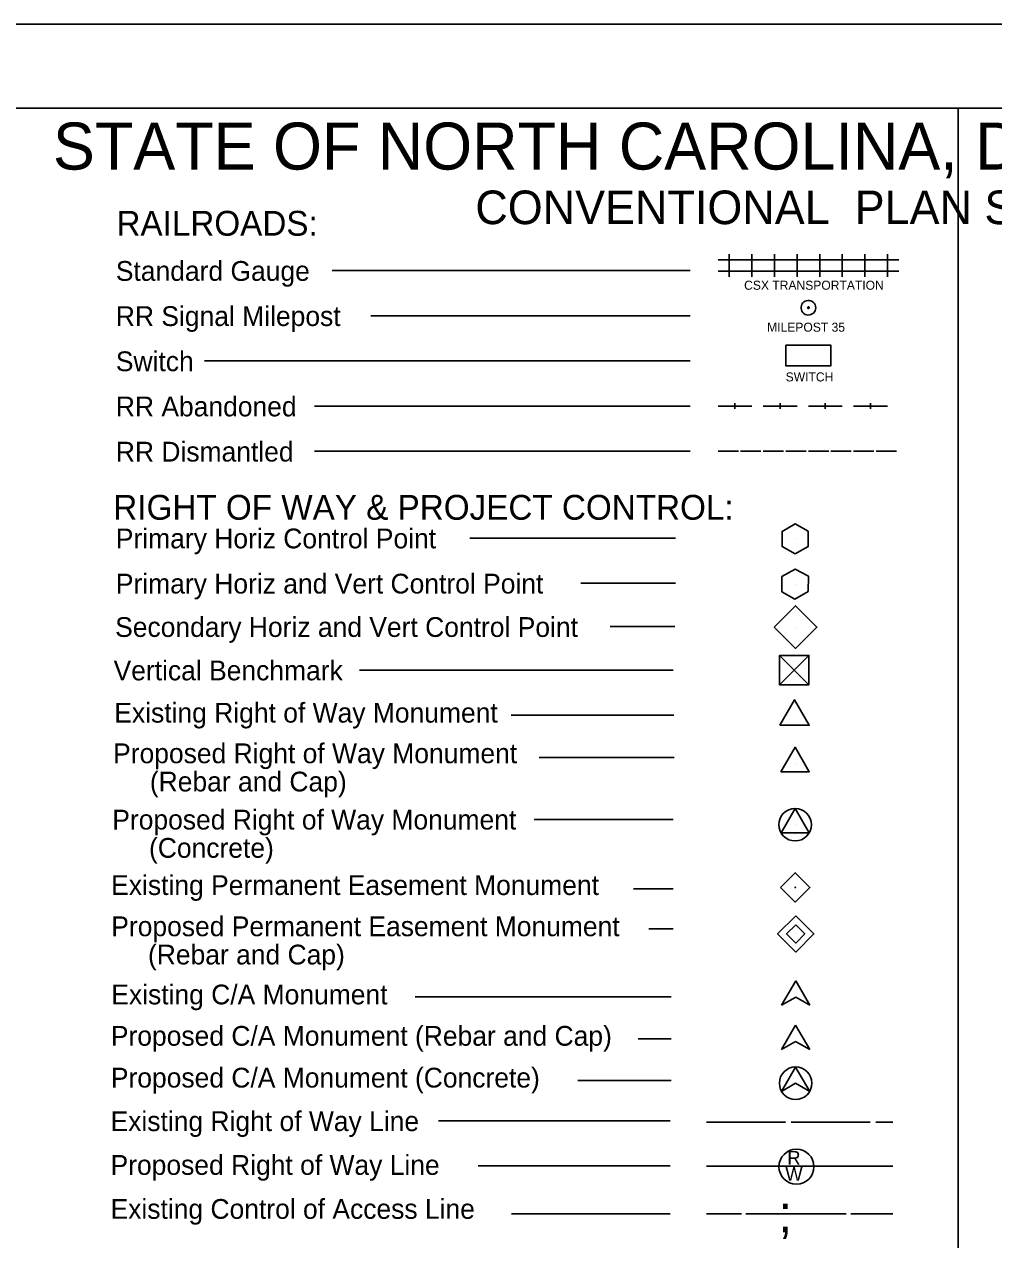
# Model space of a CAD drawing. Extents: x -0.53 to 3.34, y -0.27 to 4.33.
# Drawn here: x 0.939 to 1.661, y 3.424 to 4.328 of the extents above; entities that cross this region are included whole.
import ezdxf

# ---------------------------------------------------------------- set-up
doc = ezdxf.new("R2010")
doc.units = 0
for name, color, linetype in [('P_RDY_ROW_Permanent_Easement', 7, 'Continuous'), ('Sheet_Plan', 7, 'Continuous'), ('Sheet_Symbology', 7, 'Continuous'), ('z - Construction', 7, 'Continuous')]:
    doc.layers.add(name, color=color, linetype=linetype)

msp = doc.modelspace()

# ---------------------------------------------------------------- linework, layer by layer
at = {"layer": 'P_RDY_ROW_Permanent_Easement'}
msp.add_line((1.5132, 3.65135), (1.5132, 3.65135), dxfattribs=at)
for points in [[(1.5132, 3.66489), (1.52674, 3.65135), (1.5132, 3.63781), (1.49966, 3.65135)], [(1.5132, 3.65812), (1.51997, 3.65135), (1.5132, 3.64458), (1.50643, 3.65135)]]:
    msp.add_lwpolyline(points, close=True, dxfattribs=at)
at = {"layer": 'Sheet_Plan'}
msp.add_line((2.98823, 4.26594), (0.2799, 4.26594), dxfattribs=at)
at = {"layer": 'Sheet_Symbology'}
for p, q in [((1.45536, 4.15312), (1.47217, 4.15312)), ((1.46377, 4.14051), (1.46377, 4.15732)), ((1.47217, 4.15312), (1.48899, 4.15312)), ((1.48058, 4.14051), (1.48058, 4.15732)), ((1.48899, 4.15312), (1.50581, 4.15312)), ((1.4974, 4.14051), (1.4974, 4.15732)), ((1.50581, 4.15312), (1.52262, 4.15312)), ((1.51421, 4.14051), (1.51421, 4.15732)), ((1.52262, 4.15312), (1.53944, 4.15312)), ((1.53103, 4.14051), (1.53103, 4.15732)), ((1.53944, 4.15312), (1.55625, 4.15312)), ((1.54785, 4.14051), (1.54785, 4.15732)), ((1.55625, 4.15312), (1.57307, 4.15312)), ((1.56466, 4.14051), (1.56466, 4.15732)), ((1.57307, 4.15312), (1.58988, 4.15312)), ((1.58148, 4.14051), (1.58148, 4.15732)), ((1.43452, 4.14511), (1.16814, 4.14511)), ((1.45536, 4.14471), (1.47217, 4.14471)), ((1.47217, 4.14471), (1.48899, 4.14471)), ((1.48899, 4.14471), (1.50581, 4.14471)), ((1.50581, 4.14471), (1.52262, 4.14471)), ((1.52262, 4.14471), (1.53944, 4.14471)), ((1.53944, 4.14471), (1.55625, 4.14471)), ((1.55625, 4.14471), (1.57307, 4.14471)), ((1.57307, 4.14471), (1.58988, 4.14471)), ((1.43452, 4.11148), (1.19696, 4.11148)), ((1.43452, 4.07785), (1.07313, 4.07785)), ((1.43452, 4.04422), (1.15511, 4.04422)), ((1.45536, 4.04422), (1.48058, 4.04422)), ((1.46797, 4.04632), (1.46797, 4.04212)), ((1.48899, 4.04422), (1.51421, 4.04422)), ((1.5016, 4.04632), (1.5016, 4.04212)), ((1.52262, 4.04422), (1.54785, 4.04422)), ((1.53523, 4.04632), (1.53523, 4.04212)), ((1.55625, 4.04422), (1.58148, 4.04422)), ((1.56886, 4.04632), (1.56886, 4.04212)), ((1.43452, 4.01059), (1.15511, 4.01059)), ((1.43452, 4.01059), (1.15511, 4.01059)), ((1.45536, 4.01059), (1.47049, 4.01059)), ((1.47217, 4.01059), (1.48731, 4.01059)), ((1.48899, 4.01059), (1.50412, 4.01059)), ((1.50581, 4.01059), (1.52094, 4.01059)), ((1.52262, 4.01059), (1.53776, 4.01059)), ((1.53944, 4.01059), (1.55457, 4.01059)), ((1.55625, 4.01059), (1.57139, 4.01059)), ((1.57307, 4.01059), (1.5882, 4.01059)), ((1.42374, 3.94603), (1.27067, 3.94603)), ((1.51275, 3.9454), (1.51275, 3.9454)), ((1.42374, 3.9124), (1.35325, 3.9124)), ((1.51273, 3.91183), (1.51273, 3.91183)), ((1.42322, 3.8801), (1.3752, 3.8801)), ((1.51297, 3.87975), (1.51297, 3.87975)), ((1.42206, 3.84778), (1.18859, 3.84778)), ((1.51212, 3.8478), (1.51212, 3.8478)), ((1.42258, 3.81418), (1.30142, 3.81418)), ((1.42275, 3.78259), (1.32231, 3.78259)), ((1.51274, 3.7782), (1.51274, 3.7782)), ((1.42191, 3.73651), (1.31851, 3.73651)), ((1.51277, 3.73269), (1.51277, 3.73269)), ((1.42204, 3.6849), (1.39253, 3.6849)), ((1.5129, 3.686), (1.5129, 3.686)), ((1.42204, 3.65527), (1.40387, 3.65527)), ((1.50266, 3.59825), (1.51317, 3.61641)), ((1.51317, 3.61641), (1.52368, 3.59825)), ((1.42037, 3.60446), (1.22995, 3.60446)), ((1.51317, 3.60431), (1.50266, 3.59825)), ((1.52368, 3.59825), (1.51317, 3.60431)), ((1.50261, 3.56527), (1.51312, 3.58343)), ((1.51312, 3.58343), (1.52363, 3.56527)), ((1.42054, 3.57329), (1.39604, 3.57329)), ((1.51312, 3.57133), (1.50261, 3.56527)), ((1.52363, 3.56527), (1.51312, 3.57133)), ((1.50261, 3.53415), (1.51312, 3.55231)), ((1.51312, 3.55231), (1.52363, 3.53415)), ((1.42054, 3.54217), (1.35093, 3.54217)), ((1.51312, 3.54021), (1.50261, 3.53415)), ((1.52363, 3.53415), (1.51312, 3.54021)), ((1.4198, 3.51227), (1.24741, 3.51227)), ((1.44675, 3.51131), (1.50561, 3.51131)), ((1.50981, 3.51131), (1.56867, 3.51131)), ((1.57287, 3.51131), (1.58548, 3.51131)), ((1.4198, 3.47864), (1.27679, 3.47864)), ((1.44675, 3.47843), (1.58548, 3.47843)), ((1.4198, 3.44312), (1.30168, 3.44312)), ((1.44675, 3.44312), (1.47275, 3.44312)), ((1.47612, 3.44312), (1.5508, 3.44312)), ((1.55416, 3.44312), (1.58548, 3.44312))]:
    msp.add_line(p, q, dxfattribs=at)
for points in [[(1.52811, 4.11747), (1.52799, 4.11856), (1.52767, 4.11965), (1.52712, 4.12063), (1.52636, 4.1214), (1.52548, 4.12205), (1.5245, 4.1226), (1.52352, 4.12282), (1.52231, 4.12293), (1.52122, 4.12271), (1.52024, 4.12238), (1.51926, 4.12183), (1.51849, 4.12107), (1.51784, 4.12009), (1.5174, 4.1191), (1.51718, 4.11801), (1.51718, 4.11692), (1.5174, 4.11583), (1.51784, 4.11485), (1.51849, 4.11386), (1.51926, 4.1131), (1.52024, 4.11255), (1.52122, 4.11222), (1.52231, 4.112), (1.52352, 4.11211), (1.5245, 4.11233), (1.52548, 4.11288), (1.52636, 4.11353), (1.52712, 4.1143), (1.52767, 4.11528), (1.52799, 4.11637), (1.52811, 4.11747)], [(1.52286, 4.11812), (1.52253, 4.11812), (1.52221, 4.1179), (1.52199, 4.11758), (1.5221, 4.11725), (1.52231, 4.11692), (1.52264, 4.11681), (1.52297, 4.11692), (1.52319, 4.11714), (1.5233, 4.11758), (1.52319, 4.1179), (1.52286, 4.11812)], [(1.51275, 3.93422), (1.503, 3.93975), (1.503, 3.95094), (1.51275, 3.95659), (1.5225, 3.95106), (1.5225, 3.93975), (1.51275, 3.93422)], [(1.52301, 3.85869), (1.5012, 3.83688), (1.5121, 3.84778), (1.52301, 3.83688), (1.5012, 3.85869)], [(1.5121, 3.84778), (1.52301, 3.85869), (1.5012, 3.85869), (1.5121, 3.84778)], [(1.5121, 3.84778), (1.5012, 3.83688), (1.52301, 3.83688), (1.5121, 3.84778)], [(1.50137, 3.80668), (1.51229, 3.82565), (1.52322, 3.80668), (1.50137, 3.80668)]]:
    msp.add_lwpolyline(points, dxfattribs=at)
for points in [[(1.50581, 4.08956), (1.53944, 4.08956), (1.53944, 4.07426), (1.50581, 4.07426)], [(1.50293, 3.9175), (1.51279, 3.923), (1.52265, 3.91758), (1.5225, 3.90628), (1.51264, 3.90055), (1.50293, 3.90605)], [(1.49714, 3.87981), (1.51305, 3.89571), (1.52898, 3.87978), (1.51307, 3.86387)], [(1.5012, 3.85869), (1.52301, 3.85869), (1.52301, 3.83688), (1.5012, 3.83688)], [(1.50223, 3.77214), (1.51274, 3.7903), (1.52325, 3.77214)], [(1.50226, 3.72664), (1.51277, 3.7448), (1.52328, 3.72664)], [(1.50198, 3.686), (1.5129, 3.69693), (1.52382, 3.686), (1.5129, 3.67508)]]:
    msp.add_lwpolyline(points, close=True, dxfattribs=at)
for centre, radius in [((1.51277, 3.73269), 0.01211), ((1.5129, 3.686), 0.000212), ((1.51312, 3.54021), 0.01211), ((1.51377, 3.47809), 0.01304)]:
    msp.add_circle(centre, radius, dxfattribs=at)
at = {"layer": 'z - Construction'}
for p, q in [((3.05073, 4.32844), (0.2174, 4.32844)), ((1.63406, 4.26594), (1.63402, 2.55761))]:
    msp.add_line(p, q, dxfattribs=at)

# ---------------------------------------------------------------- texts
at = {"layer": 'Sheet_Symbology'}
for s, height, p in [('STATE OF NORTH CAROLINA, DIVISION OF HIGHWAYS', 0.035, (0.9603, 4.2203)), ('CONVENTIONAL  PLAN SHEET SYMBOLS', 0.025, (1.27472, 4.17969)), ('RAILROADS:', 0.018497, (1.00759, 4.17109)), ('Standard Gauge', 0.0147137, (1.00713, 4.1375)), ('CSX TRANSPORTATION', 0.0067262, (1.4748, 4.13086)), ('RR Signal Milepost', 0.0147137, (1.00713, 4.10387)), ('MILEPOST 35', 0.0067262, (1.49193, 4.09963)), ('Switch', 0.014714, (1.00713, 4.07024)), ('SWITCH', 0.006726, (1.50572, 4.06263)), ('RR Abandoned', 0.0147137, (1.00713, 4.03661)), ('RR Dismantled', 0.0147137, (1.00713, 4.00298)), ('RIGHT OF WAY & PROJECT CONTROL:', 0.0184972, (1.00523, 3.95967)), ('Primary Horiz Control Point', 0.0147137, (1.00714, 3.93838)), ('Primary Horiz and Vert Control Point', 0.0147137, (1.00714, 3.90475)), ('Secondary Horiz and Vert Control Point', 0.0147137, (1.00661, 3.87245)), ('Vertical Benchmark', 0.0147137, (1.00545, 3.84013)), ('Existing Right of Way Monument', 0.0147137, (1.00598, 3.80867)), ('Proposed Right of Way Monument', 0.0147137, (1.0051, 3.77844)), ('     (Rebar and Cap)', 0.0147137, (1.0051, 3.75742)), ('Proposed Right of Way Monument', 0.0147137, (1.00447, 3.72909)), ('     (Concrete)', 0.0147137, (1.00447, 3.70807)), ('Existing Permanent Easement Monument', 0.0147137, (1.00366, 3.68034)), ('Proposed Permanent Easement Monument', 0.0147137, (1.00372, 3.64967)), ('     (Rebar and Cap)', 0.0147137, (1.00372, 3.62865)), ('Existing C/A Monument', 0.0147137, (1.00376, 3.59894)), ('Proposed C/A Monument (Rebar and Cap)', 0.0147137, (1.00342, 3.56815)), ('Proposed C/A Monument (Concrete)', 0.0147137, (1.00342, 3.53703)), ('Existing Right of Way Line', 0.0147137, (1.00319, 3.50462)), ('Proposed Right of Way Line', 0.0147137, (1.00319, 3.47204)), ('R', 0.01022, (1.50693, 3.47962)), ('W', 0.01022, (1.50548, 3.46759)), ('Existing Control of Access Line', 0.0147137, (1.00319, 3.43932)), (';', 0.02775, (1.50022, 3.42935))]:
    msp.add_text(s, height=height, dxfattribs=at).set_placement(p)

doc.saveas('drawing.dxf')
